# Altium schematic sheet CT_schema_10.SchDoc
size 254 x 194 mm
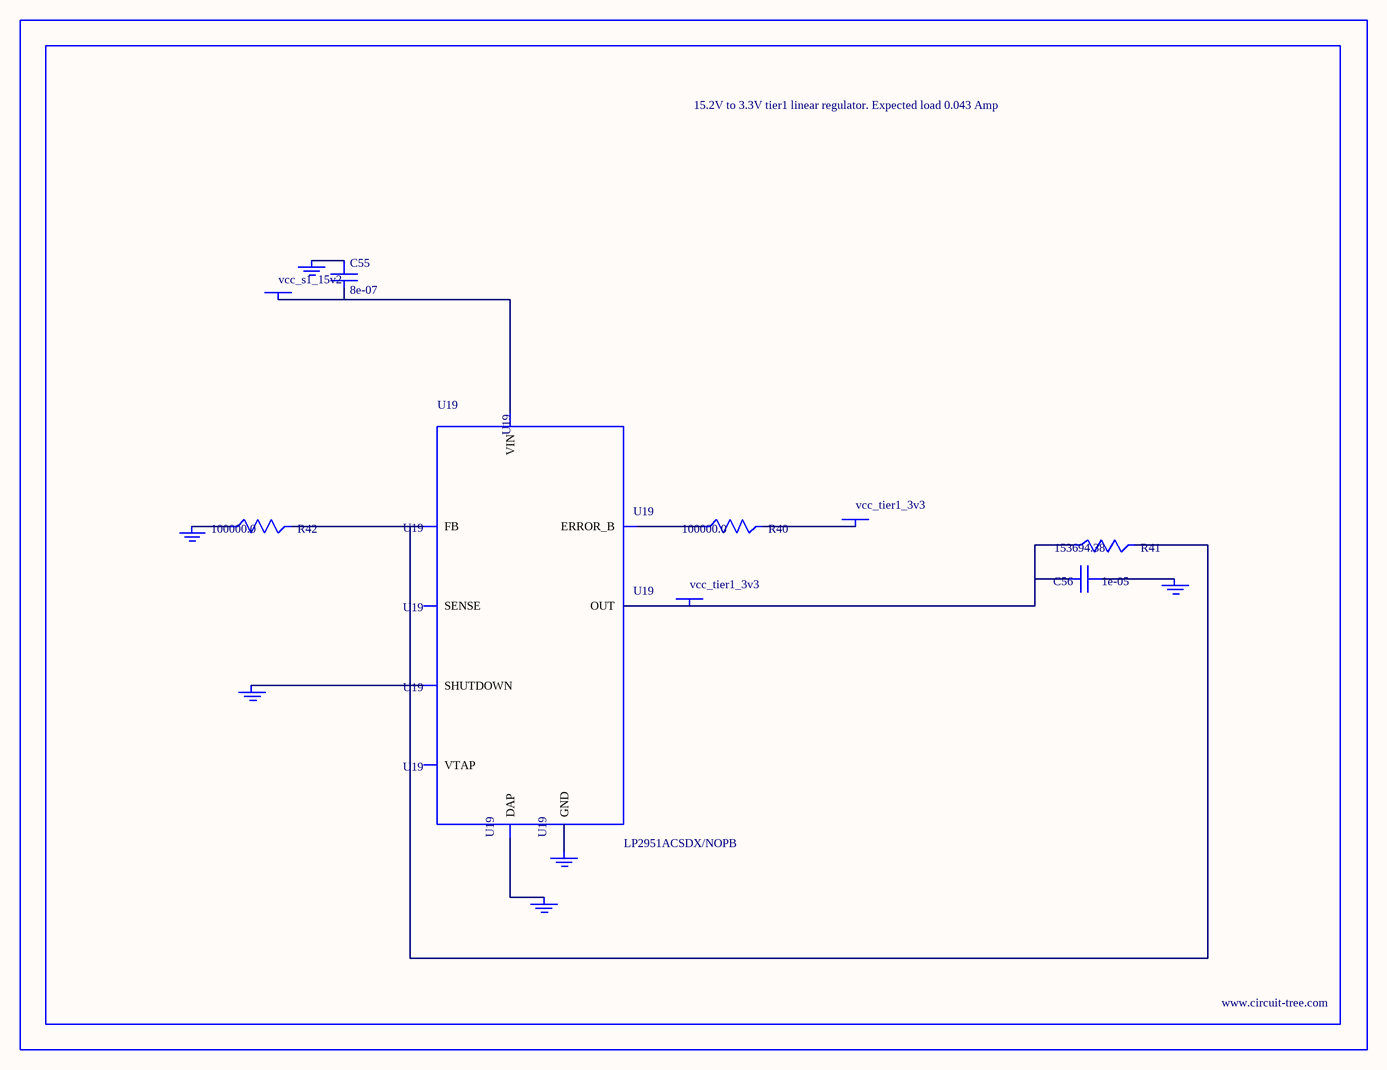
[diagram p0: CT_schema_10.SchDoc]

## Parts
BORDER9  (no value)
C55  8e-07  [R0603]
C56  1e-05  [C1210]
GND_INSTANCE_9_0  (no value)
GND_INSTANCE_9_1  (no value)
GND_INSTANCE_9_2  (no value)
GND_INSTANCE_9_3  (no value)
GND_INSTANCE_9_4  (no value)
GND_INSTANCE_9_5  (no value)
POWER_INSTANCE_9_0  vcc_tier1_3v3
POWER_INSTANCE_9_1  vcc_s1_15v2
POWER_INSTANCE_9_2  vcc_tier1_3v3
R40  100000.0  [R0603]
R41  153694.38  [R0603]
R42  100000.0  [R0603]
U19  LP2951ACSDX/NOPB  [WSON-8]

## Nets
NetC55_1: C55.1 GND_INSTANCE_9_3.0(GND)
NetC55_2: C55.2 POWER_INSTANCE_9_1.0(PWR) U19.8(VIN)
NetC56_1: C56.1 GND_INSTANCE_9_0.0(GND)
NetC56_2: C56.2 POWER_INSTANCE_9_2.0(PWR) R41.1 U19.1(OUT)
NetGND_INSTANCE_9_1_0: GND_INSTANCE_9_1.0(GND) U19.3(SHUTDOWN)
NetGND_INSTANCE_9_2_0: GND_INSTANCE_9_2.0(GND) R42.1
NetGND_INSTANCE_9_4_0: GND_INSTANCE_9_4.0(GND) U19.PAD(DAP)
NetGND_INSTANCE_9_5_0: GND_INSTANCE_9_5.0(GND) U19.4(GND)
NetPOWER_INSTANCE_9_0_0: POWER_INSTANCE_9_0.0(PWR) R40.2
NetR40_1: R40.1 U19.5(ERROR_B)
NetR41_2: R41.2 R42.2 U19.7(FB)

Not connected (* = marked no-connect by the designer): U19 2(SENSE) 6(VTAP)

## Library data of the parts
BORDER9 = BORDER_PAGE9
C55 = C55
C56 = GRM32DR61E106MA12L
GND_INSTANCE_9_0-GND_INSTANCE_9_5 = GND
POWER_INSTANCE_9_0-POWER_INSTANCE_9_2 = PWR
R40 R42 = RC0603JR-07100KL
R41 = R41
